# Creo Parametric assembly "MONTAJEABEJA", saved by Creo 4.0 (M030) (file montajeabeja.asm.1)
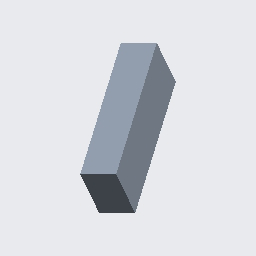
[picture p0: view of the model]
Units: millimeter Newton Second (mmNs); MM, TONNE, SECS

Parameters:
  MODELED_BY = "aj"

Created from: MMNS_ASM_DESIGN.ASM

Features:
  1. datum plane "ASM_RIGHT"
  2. datum plane "ASM_TOP"
  3. datum plane "ASM_FRONT"
  4. coordinate system
  5. component "LADOSUNIONESABEJA"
